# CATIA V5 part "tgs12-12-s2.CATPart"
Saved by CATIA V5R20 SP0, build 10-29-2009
Part number: TGS12-12-S2
Revision: 1
Definition: design
Nomenclature: TGS12-12-S2
Source: made
Description: NOT SPECIFIED
Bounding box of the stored display mesh (mm): x -22 to 0.8, y 0 to 12, z -5 to 5
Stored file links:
  C:\Users\Raffaele\Desktop\3D X SITO CF\I-MOLD\TGS-S2\tgs12-s2.step\tgs12-12-s2.CATPart
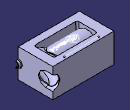
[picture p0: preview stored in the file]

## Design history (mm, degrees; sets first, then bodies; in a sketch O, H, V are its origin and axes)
Set1
  Line1 "LINE #4011": stored without definition
  DatumCurve1 "COMPOSITE_CURVE #4066"
  DatumCurve2 "COMPOSITE_CURVE #4115"
  DatumCurve3 "COMPOSITE_CURVE #4194"
  DatumCurve4 "COMPOSITE_CURVE #4237"
  DatumCurve5 "COMPOSITE_CURVE #4466"
  DatumCurve6 "COMPOSITE_CURVE #4607"
  DatumCurve7 "COMPOSITE_CURVE #4634"
  DatumCurve8 "COMPOSITE_CURVE #4692"
  DatumCurve9 "COMPOSITE_CURVE #4749"
  DatumCurve10 "COMPOSITE_CURVE #4778"
  DatumSurface1 "OPEN_SHELL #4001"
Body1 "MANIFOLD_SOLID_BREP #4002" (main body)
  Solid1: solid without history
